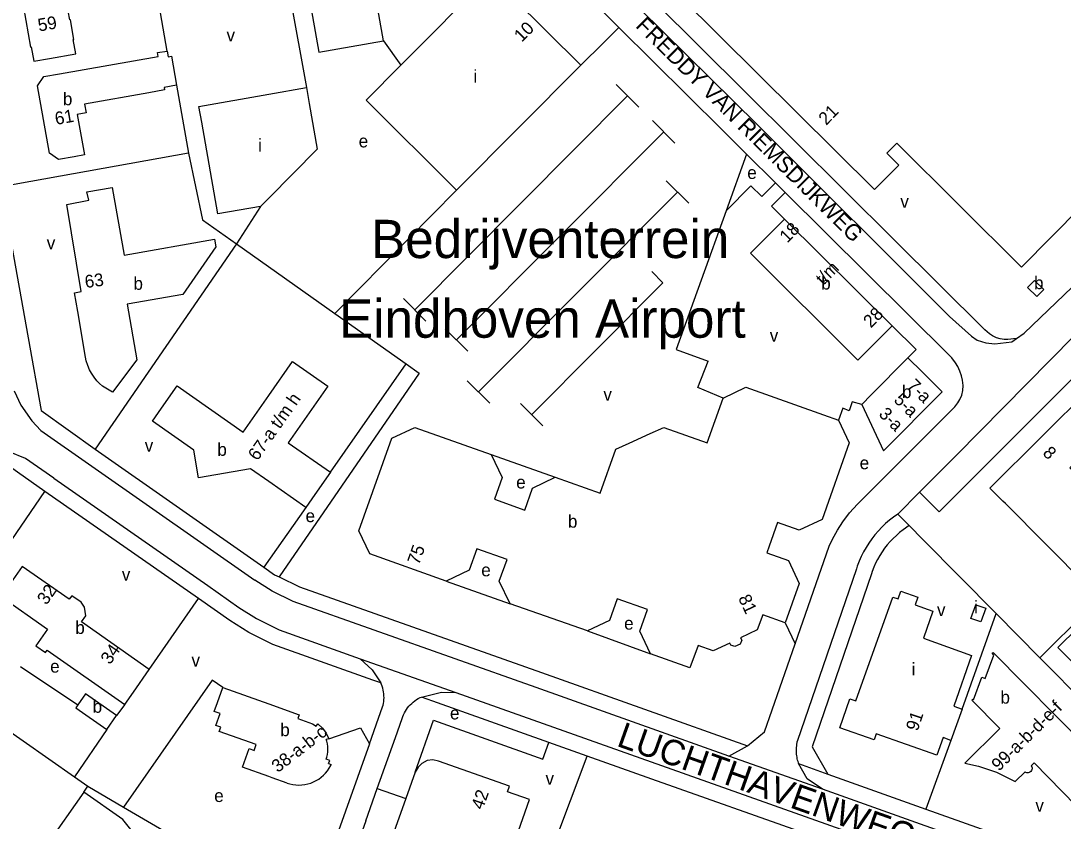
# Model space of a CAD drawing. Extents: x 154765 to 156627, y 383996 to 386132.
# Drawn here: x 155422.2 to 155749.2, y 385163.7 to 385414.8 of the extents above; entities that cross this region are included whole.
import ezdxf

# ---------------------------------------------------------------- set-up
doc = ezdxf.new("R2010")
doc.units = 0
for name, color, linetype in [('BLT_Basislijn', 7, 'Continuous'), ('BLT_Bebouwing', 7, 'Continuous'), ('BLT_Centroide', 7, 'Continuous'), ('BLT_Huisnummer', 7, 'Continuous'), ('BLT_Huisnummer_reeks', 7, 'Continuous'), ('BLT_Onderverdeling_panden', 7, 'Continuous'), ('BLT_Sport_parknaam', 7, 'Continuous'), ('BLT_Straatnaam', 7, 'Continuous'), ('BLT_Straatnaam_hoofdweg', 7, 'Continuous'), ('BLT_Vlakafsluiter', 7, 'Continuous')]:
    doc.layers.add(name, color=color, linetype=linetype)

msp = doc.modelspace()

# ---------------------------------------------------------------- linework, layer by layer
at = {"layer": 'BLT_Basislijn'}
for p, q in [((155468.15, 385405.36), (155460.46, 385448.85)), ((155506.52, 385423.64), (155511.8, 385393.87)), ((155604.99, 385407.95), (155609.89, 385412.76)), ((155536.01, 385408.59), (155541.46, 385400.93)), ((155597.88, 385400.95), (155604.99, 385407.95)), ((155471.08, 385394.64), (155474.85, 385373.32)), ((155616.13, 385387.76), (155609.04, 385394.81)), ((155612.59, 385391.29), (155545.79, 385324.15)), ((155627.46, 385376.49), (155620.37, 385383.54)), ((155623.92, 385380.01), (155558.92, 385314.7)), ((155474.85, 385373.32), (155416.02, 385362.7)), ((155474.85, 385373.32), (155479.23, 385352.38)), ((155631.76, 385357.59), (155624.67, 385364.65)), ((155658.98, 385363.96), (155654.71, 385359.68)), ((155658.98, 385363.96), (155662.03, 385360.93)), ((155558.94, 385361.75), (155520.71, 385323.05)), ((155628.22, 385361.12), (155565.8, 385298.39)), ((155662.03, 385360.93), (155657.76, 385356.65)), ((155497.37, 385356.59), (155489.85, 385344.87)), ((155479.23, 385352.38), (155489.85, 385344.87)), ((155489.85, 385344.87), (155445.57, 385280.43)), ((155489.85, 385344.87), (155520.71, 385323.05)), ((155796.43, 385347.07), (155710.35, 385260.77)), ((155623.7, 385332.67), (155620.15, 385336.2)), ((155623.7, 385332.67), (155582.48, 385291.25)), ((155549.33, 385320.63), (155542.24, 385327.68)), ((155520.71, 385323.05), (155543.12, 385307.2)), ((155562.47, 385311.17), (155555.38, 385318.22)), ((155519.35, 385273.19), (155543.12, 385307.2)), ((155543.12, 385307.2), (155547.18, 385304.33)), ((155547.18, 385304.33), (155503.24, 385240.36)), ((155569.35, 385294.87), (155562.26, 385301.92)), ((155428.63, 385292.55), (155445.57, 385280.43)), ((155586.03, 385287.73), (155578.94, 385294.78)), ((155445.57, 385280.43), (155498.47, 385243.39)), ((155569.84, 385278.73), (155589.92, 385271.61)), ((155429.71, 385267.2), (155416.84, 385276.27)), ((155478, 385233.54), (155429.71, 385267.2)), ((155704.17, 385266.91), (155710.35, 385260.77)), ((155511.6, 385262.11), (155498.47, 385243.39)), ((155697.37, 385260.09), (155700.94, 385256.48)), ((155788.81, 385261.42), (155741.91, 385215.01)), ((155700.94, 385256.48), (155705.32, 385252.04)), ((155705.32, 385252.04), (155728.26, 385228.83)), ((155684.38, 385242.92), (155665.8, 385188.7)), ((155689.12, 385241.32), (155670.54, 385187.08)), ((155555.64, 385239.03), (155575.74, 385231.87)), ((155462.53, 385211.34), (155478, 385233.54)), ((155717.53, 385198.87), (155728.26, 385228.83)), ((155728.26, 385228.83), (155741.91, 385215.01)), ((155600, 385223.45), (155619.79, 385216.19)), ((155662.04, 385225.98), (155665.17, 385219.37)), ((155741.91, 385215.01), (155777.19, 385179.31)), ((155422.14, 385212.21), (155440.1, 385200.18)), ((155454.87, 385200.35), (155452.2, 385196.86)), ((155449.16, 385192.52), (155439.03, 385177.62)), ((155650.23, 385187.38), (155655.53, 385191.72)), ((155531.64, 385187.95), (155515.19, 385141.8)), ((155534.05, 385173.99), (155539.73, 385189.98)), ((155599.94, 385184.14), (155587.92, 385188.42)), ((155644.39, 385184.15), (155650.23, 385187.38)), ((155650.23, 385187.38), (155650.28, 385187.42)), ((155670.54, 385187.08), (155675.4, 385178.45)), ((155714.02, 385189.06), (155706.21, 385167.51)), ((155588.82, 385154.61), (155599.94, 385184.14)), ((155666.26, 385181.84), (155675.4, 385178.45)), ((155675.4, 385178.45), (155706.21, 385167.51)), ((155530.45, 385163.87), (155534.05, 385173.99))]:
    msp.add_line(p, q, dxfattribs=at)
for points in [[(155609.89, 385412.76), (155575.43, 385447), (155566.59, 385455.92), (155565.51, 385457), (155564.19, 385458.03), (155562.99, 385458.85), (155561.59, 385459.71), (155560.11, 385460.47), (155558.02, 385461.34), (155555.91, 385462.06), (155552.98, 385462.73), (155550.98, 385462.93), (155548.56, 385463.03), (155547.68, 385462.98)], [(155734.6, 385315.13), (155731.84, 385314.84), (155730.71, 385314.86), (155729.51, 385315.05), (155728.37, 385315.4), (155727.12, 385315.99), (155726.14, 385316.67), (155724.68, 385317.83), (155696.18, 385346.15), (155649.48, 385392.56), (155621.13, 385420.73), (155611.87, 385429.93)], [(155608.96, 385426.03), (155653.28, 385382.33), (155713.58, 385322.08), (155720.5, 385315.89), (155722.31, 385314.59), (155724.99, 385313.76), (155727.79, 385313.46), (155733.17, 385314.1), (155734.6, 385315.13)], [(155649.88, 385372.98), (155642.14, 385380.78), (155609.89, 385412.76)], [(155734.6, 385315.13), (155737.02, 385316.87), (155752.07, 385331.32), (155809.42, 385389.71), (155810.63, 385390.94)], [(155649.88, 385372.98), (155643.48, 385355.22)], [(155658.98, 385363.96), (155649.88, 385372.98)], [(155416.02, 385362.7), (155424.54, 385315.33), (155428.63, 385292.55)], [(155654.71, 385359.68), (155651.28, 385363.08), (155643.48, 385355.22)], [(155665.17, 385219.37), (155675.84, 385250), (155676.37, 385251.16), (155677.39, 385253.13), (155678.43, 385255.01), (155680.11, 385257.59), (155682.25, 385260.45), (155684.71, 385263.14), (155715.22, 385293.74), (155716.19, 385295), (155716.84, 385296.06), (155717.42, 385297.43), (155717.73, 385298.8), (155717.86, 385300.44), (155717.7, 385302.04), (155717.39, 385303.43), (155716.86, 385304.96), (155716.2, 385306.38), (155715.48, 385307.56), (155714.3, 385309.05), (155713.35, 385310.04), (155662.03, 385360.93)], [(155643.48, 385355.22), (155627.79, 385311.76), (155637.82, 385308)], [(155661.8, 385352.64), (155657.76, 385356.65)], [(155715.76, 385278.56), (155752.64, 385315.9), (155766.75, 385330.32)], [(155695.55, 385319.16), (155703.11, 385311.66), (155700.55, 385309.08)], [(155642.56, 385296.45), (155634.6, 385299.76), (155637.82, 385308)], [(155420.11, 385298.76), (155422.23, 385294.2), (155425.65, 385289.38), (155428.46, 385286.31), (155495.6, 385239.29)], [(155686.07, 385294.48), (155683.09, 385295.32), (155682.12, 385292.5), (155680.12, 385293.28), (155678.73, 385289.55)], [(155432.59, 385271.29), (155423.74, 385277.53), (155418.53, 385279.58), (155413.38, 385280.64), (155408.56, 385281.41)], [(155715.76, 385278.56), (155713.88, 385276.66), (155704.17, 385266.91)], [(155432.59, 385271.29), (155480.88, 385237.63), (155490.58, 385230.81), (155496.21, 385227.28), (155503.26, 385223.74), (155528.74, 385214.67)], [(155393.24, 385209.32), (155391.13, 385210.77), (155429.71, 385267.2)], [(155704.17, 385266.91), (155697.37, 385260.09)], [(155697.37, 385260.09), (155696.05, 385259.15), (155694.77, 385258.16), (155693.55, 385257.1), (155692.37, 385255.98), (155691.26, 385254.81), (155690.2, 385253.58), (155689.21, 385252.31), (155688.28, 385250.98), (155687.41, 385249.61), (155686.62, 385248.2), (155685.89, 385246.75), (155685.24, 385245.27), (155684.66, 385243.76), (155684.38, 385242.92)], [(155700.94, 385256.48), (155699.03, 385255.14), (155697.94, 385254.29), (155696.91, 385253.4), (155695.91, 385252.45), (155694.97, 385251.46), (155694.07, 385250.41), (155693.23, 385249.33), (155692.44, 385248.21), (155691.71, 385247.05), (155691.03, 385245.85), (155690.42, 385244.63), (155689.87, 385243.37), (155689.37, 385242.06), (155689.12, 385241.32)], [(155498.47, 385243.39), (155501.83, 385241.05), (155503.24, 385240.36)], [(155644.39, 385184.15), (155583.93, 385205.62), (155507.68, 385232.64), (155501.05, 385235.87), (155495.6, 385239.29)], [(155503.24, 385240.36), (155509.62, 385237.26), (155585.6, 385210.34), (155650.23, 385187.38)], [(155535.16, 385207.08), (155532.69, 385207.96), (155501.29, 385219.14), (155493.75, 385222.91), (155487.81, 385226.65), (155478, 385233.54)], [(155655.53, 385191.72), (155665.17, 385219.37)], [(155528.74, 385214.67), (155532.49, 385211.22), (155535.16, 385207.08)], [(155485.56, 385205.68), (155482.23, 385208.01), (155454.45, 385168.14)], [(155535.74, 385199.54), (155535.89, 385200.1), (155536.01, 385200.67), (155536.09, 385201.25), (155536.15, 385201.84), (155536.17, 385202.44), (155536.16, 385203.05), (155536.12, 385203.65), (155536.04, 385204.26), (155535.92, 385204.86), (155535.77, 385205.45), (155535.58, 385206.04), (155535.37, 385206.61), (155535.16, 385207.08)], [(155547.94, 385202.67), (155554.23, 385204.19), (155558.69, 385204.04)], [(155558.69, 385204.04), (155671.59, 385164), (155719.27, 385147.11), (155745.95, 385136.27), (155751.44, 385134.14)], [(155541.87, 385195.98), (155542.07, 385196.55), (155542.3, 385197.11), (155542.56, 385197.67), (155542.86, 385198.21), (155543.2, 385198.75), (155543.57, 385199.26), (155543.97, 385199.76), (155544.4, 385200.23), (155544.86, 385200.68), (155545.34, 385201.1), (155545.85, 385201.49), (155546.38, 385201.85), (155546.93, 385202.18), (155547.49, 385202.47), (155547.94, 385202.67)], [(155587.92, 385188.42), (155551.45, 385201.4), (155547.94, 385202.67)], [(155531.64, 385187.95), (155534.49, 385196.06), (155535.74, 385199.54)], [(155539.73, 385189.98), (155541.87, 385195.98)], [(155545.92, 385179.11), (155551.69, 385195.36), (155586.05, 385183.15), (155587.92, 385188.42)], [(155518.87, 385189.59), (155528.78, 385192.95), (155531.64, 385187.95)], [(155666.26, 385181.84), (155666.21, 385181.98), (155666.07, 385182.42), (155665.95, 385182.86), (155665.84, 385183.31), (155665.75, 385183.77), (155665.68, 385184.23), (155665.63, 385184.69), (155665.6, 385185.14), (155665.59, 385185.6), (155665.59, 385186.06), (155665.61, 385186.51), (155665.8, 385188.7)], [(155669.92, 385159.28), (155620.24, 385176.93), (155599.94, 385184.14)], [(155673.76, 385173.72), (155668.95, 385177.02), (155666.26, 385181.84)], [(155443.27, 385174.66), (155454.45, 385168.14)], [(155534.05, 385173.99), (155542.97, 385170.82)], [(155755.57, 385147.79), (155746.1, 385149.29), (155734.81, 385152.01), (155728.35, 385154.34), (155704.53, 385162.79), (155673.76, 385173.72)], [(155454.45, 385168.14), (155481.31, 385152.46), (155515.19, 385141.8)], [(155706.21, 385167.51), (155730.03, 385159.05), (155748.54, 385152.39), (155749.64, 385152.13)], [(155530.45, 385163.87), (155526.46, 385152.67), (155523.46, 385144.21), (155522.69, 385142.05)]]:
    msp.add_lwpolyline(points, dxfattribs=at)
at = {"layer": 'BLT_Bebouwing'}
for p, q in [((155597.88, 385400.95), (155569.49, 385429.14)), ((155465.1, 385404.85), (155468.15, 385405.36)), ((155558.94, 385361.75), (155597.88, 385400.95)), ((155500, 385391.79), (155511.8, 385393.87)), ((155693.91, 385373.34), (155697.02, 385376.46)), ((155697.02, 385376.46), (155716.59, 385357.03)), ((155700.55, 385309.08), (155705.11, 385304.56)), ((155711.3, 385298.41), (155705.11, 385304.56)), ((155731.12, 385263.35), (155757.2, 385237.1)), ((155727.29, 385216.68), (155764.2, 385179.29)), ((155720.64, 385201.69), (155729.43, 385192.8)), ((155449.16, 385192.52), (155452.2, 385196.86)), ((155413.9, 385195.2), (155439.03, 385177.62)), ((155729.43, 385192.8), (155718.42, 385181.91)), ((155740.13, 385181.99), (155753.34, 385168.55)), ((155439.03, 385177.62), (155443.27, 385174.66))]:
    msp.add_line(p, q, dxfattribs=at)
for points in [[(155536.01, 385408.59), (155531.6, 385433.44), (155536.17, 385434.12), (155541.26, 385433.17), (155542.97, 385447.47), (155539.09, 385447.76), (155535.73, 385447.91), (155532.18, 385447.51), (155532.08, 385446.13), (155530.99, 385445.13), (155529.44, 385444.32), (155528.08, 385444.39), (155526.84, 385444.92), (155525.96, 385446.13), (155525.7, 385446.41), (155522.21, 385445.52), (155519.04, 385444.2), (155515.87, 385442.87), (155513, 385441.15), (155510.11, 385438.88)], [(155422.54, 385423.48), (155422.32, 385423.45), (155425.29, 385406.62), (155425.49, 385406.64), (155426.29, 385402.17), (155431.21, 385403.03), (155439.48, 385404.47), (155438.67, 385408.98), (155438.86, 385409.02), (155437.78, 385415.19), (155437.56, 385415.16), (155437.1, 385417.87), (155439.79, 385418.33), (155439.86, 385418.16), (155451.73, 385420.27), (155456.65, 385421.14), (155456.61, 385421.36), (155461.12, 385422.1), (155458.81, 385435.33), (155454.33, 385434.53), (155454.31, 385434.73), (155426.84, 385429.85), (155426.87, 385429.64)], [(155510.96, 385432.23), (155515.76, 385405.01), (155536.01, 385408.59)], [(155569.49, 385429.14), (155541.46, 385400.93)], [(155629.15, 385422.38), (155690.08, 385361.91), (155697.7, 385369.56), (155693.91, 385373.34)], [(155471.08, 385394.64), (155467.16, 385393.87), (155467.29, 385393.14), (155462.37, 385392.27), (155442.25, 385388.69), (155442.74, 385385.95), (155439.94, 385385.41), (155442.17, 385372.77), (155438.99, 385372.21), (155434.07, 385371.34), (155431.19, 385373.35), (155427.44, 385394.45), (155429.45, 385397.35), (155434.38, 385398.22), (155465.33, 385403.66), (155465.1, 385404.85)], [(155468.15, 385405.36), (155468.46, 385403.55), (155469.48, 385403.7), (155471.08, 385394.64)], [(155541.46, 385400.93), (155530.56, 385389.95), (155558.94, 385361.75)], [(155716.59, 385357.03), (155736.15, 385337.59), (155764.23, 385365.84), (155771.27, 385358.84), (155803.43, 385391.18), (155796.34, 385398.22), (155799.88, 385401.72)], [(155511.8, 385393.87), (155512.67, 385388.95), (155515.23, 385374.55), (155500, 385359.23), (155497.37, 385356.59)], [(155497.37, 385356.59), (155484.02, 385354.31), (155478.99, 385383), (155478.12, 385387.92), (155500, 385391.79)], [(155450.93, 385362.54), (155454.69, 385341.27), (155483.03, 385346.28), (155483.44, 385343.9), (155473.02, 385329.01), (155455.56, 385325.91), (155458.62, 385308.45), (155450.96, 385298.31), (155447.87, 385300.21), (155446.91, 385301.07), (155446.1, 385301.89), (155445.23, 385303), (155444.38, 385304.28), (155443.79, 385305.37), (155443.22, 385306.68), (155442.77, 385308.11), (155442.51, 385309.3), (155440.16, 385323.66), (155439.1, 385329.48), (155441.2, 385329.86), (155436.62, 385357.26), (155443.58, 385358.52), (155442.96, 385361.14), (155450.93, 385362.54)], [(155661.8, 385352.64), (155651.13, 385341.89), (155684.87, 385308.4), (155695.55, 385319.16)], [(155695.55, 385319.16), (155661.8, 385352.64)], [(155500, 385297.33), (155507.44, 385307.94), (155518.51, 385300.16), (155506.07, 385282.47), (155519.35, 385273.19)], [(155700.55, 385309.08), (155689.03, 385297.46)], [(155511.6, 385262.11), (155500, 385270.25), (155494.29, 385274.25), (155477.95, 385271.43), (155476.5, 385280.08), (155463.51, 385289.2), (155466.38, 385293.3), (155471.31, 385300.33), (155491.93, 385285.82), (155500, 385297.33)], [(155642.56, 385296.45), (155649.68, 385299.87), (155674.02, 385291.22), (155678.73, 385289.55)], [(155686.07, 385294.48), (155692.92, 385279.91), (155711.3, 385298.41)], [(155726.28, 385268.19), (155742.47, 385284.29), (155757.61, 385299.32), (155761.13, 385295.77), (155766.88, 385289.95), (155751.34, 385274.61), (155757.26, 385268.66), (155772.77, 385283.98), (155788.35, 385268.01)], [(155589.92, 385271.61), (155603.99, 385266.63), (155608.87, 385280.41), (155613.13, 385282.35), (155619.67, 385285.33), (155623.92, 385287.26), (155637.58, 385282.42), (155642.56, 385296.45)], [(155689.03, 385297.46), (155686.07, 385294.48)], [(155678.73, 385289.55), (155682.14, 385282.38), (155673.6, 385258.37), (155666.44, 385254.98), (155659.65, 385257.4), (155657.02, 385250), (155656.27, 385247.87), (155663.04, 385245.47), (155666.45, 385238.31), (155662.04, 385225.98)], [(155555.64, 385239.03), (155531.67, 385247.59), (155530.52, 385250), (155528.26, 385254.77), (155529.94, 385259.48), (155538.64, 385283.84), (155545.79, 385287.23), (155569.84, 385278.73)], [(155569.84, 385278.73), (155573.24, 385271.59), (155570.8, 385264.72), (155580.31, 385261.35), (155582.75, 385268.22), (155589.92, 385271.61)], [(155519.35, 385273.19), (155514.47, 385266.21), (155511.6, 385262.11)], [(155731.12, 385263.35), (155730.33, 385264.14), (155726.28, 385268.19)], [(155575.74, 385231.87), (155572.34, 385239.05), (155574.76, 385245.82), (155565.24, 385249.21), (155562.85, 385242.43), (155555.64, 385239.03)], [(155438.2, 385234.47), (155437.39, 385233.36), (155422.68, 385243.67), (155416.09, 385234.25)], [(155416.09, 385234.25), (155430.62, 385223.94), (155426.97, 385218.73), (155429.98, 385216.62), (155430.52, 385217.4), (155454.87, 385200.35)], [(155462.53, 385211.34), (155441.26, 385226.23), (155442.59, 385228.15), (155442.15, 385230.83), (155441.11, 385232.41), (155438.2, 385234.47)], [(155619.79, 385216.19), (155616.39, 385223.35), (155618.81, 385230.08), (155609.31, 385233.48), (155606.87, 385226.71), (155600, 385223.45)], [(155714.02, 385189.06), (155711.57, 385189.95), (155709.58, 385184.41), (155690.62, 385191.1), (155689.96, 385189.2), (155679.15, 385193.05), (155682.37, 385202.1), (155684.21, 385201.44), (155695.76, 385234.05), (155697.44, 385233.46), (155698.32, 385235.93), (155703.69, 385234.04), (155702.81, 385231.55), (155708.37, 385229.58), (155705.39, 385221.12), (155720.5, 385215.65), (155714.91, 385199.8), (155717.53, 385198.87)], [(155600, 385223.45), (155575.74, 385231.87)], [(155662.04, 385225.98), (155654.98, 385228.47), (155653.26, 385223.7), (155648.05, 385221.21), (155648.39, 385220.5), (155647.94, 385219.25), (155646.27, 385218.48), (155645.01, 385218.9), (155644.69, 385219.61), (155639.45, 385217.14), (155634.69, 385218.86), (155632.14, 385211.78), (155619.79, 385216.19)], [(155720.64, 385201.69), (155720.95, 385202.03), (155721.15, 385201.82), (155723.76, 385208.9), (155724.83, 385208.49), (155727.54, 385215.82), (155726.98, 385216.38), (155727.29, 385216.68)], [(155454.87, 385200.35), (155457.53, 385204.15), (155462.53, 385211.34)], [(155452.2, 385196.86), (155442.52, 385203.63), (155440.1, 385200.18)], [(155505.76, 385175.69), (155501.05, 385177.36), (155500, 385177.74), (155491.82, 385180.64), (155493.91, 385186.48), (155495.43, 385185.94), (155496.08, 385187.76), (155484.45, 385191.89), (155484.93, 385193.24), (155483.39, 385193.78), (155484.73, 385197.51), (155482.89, 385198.16), (155483.89, 385200.97), (155485.56, 385205.68)], [(155485.56, 385205.68), (155500, 385200.53), (155509.52, 385197.13)], [(155440.1, 385200.18), (155439.48, 385199.3), (155449.16, 385192.52)], [(155509.52, 385197.13), (155509.11, 385195.98), (155513.76, 385194.24), (155514.88, 385193.53), (155515.41, 385194.25), (155516.87, 385192.94), (155518.02, 385191.37), (155518.87, 385189.59)], [(155717.53, 385198.87), (155714.02, 385189.06)], [(155519.12, 385182.8), (155518.03, 385183.17), (155518.23, 385183.78), (155518.42, 385184.62), (155518.53, 385185.47), (155518.56, 385186.33), (155518.52, 385187.18), (155518.39, 385188.03), (155518.18, 385188.87), (155518.04, 385189.31)], [(155518.87, 385189.59), (155518.04, 385189.31)], [(155505.76, 385175.69), (155506.67, 385175.41), (155507.59, 385175.21), (155508.53, 385175.09), (155509.47, 385175.05), (155510.42, 385175.09), (155511.36, 385175.21), (155512.28, 385175.4), (155513.19, 385175.68), (155514.07, 385176.03), (155514.91, 385176.45), (155515.72, 385176.94), (155516.48, 385177.5), (155517.2, 385178.12), (155517.85, 385178.8), (155518.45, 385179.54), (155518.98, 385180.32), (155519.45, 385181.14), (155519.63, 385181.5)], [(155518.78, 385181.79), (155519.12, 385182.8)], [(155518.78, 385181.79), (155519.63, 385181.5)], [(155551.44, 385182.95), (155549.7, 385182.71), (155548.02, 385181.86), (155546.85, 385180.69), (155545.92, 385179.11)], [(155577.59, 385158.61), (155581.82, 385170.48), (155574.93, 385172.93), (155575.55, 385174.67), (155553.22, 385182.59), (155551.44, 385182.95)], [(155718.42, 385181.91), (155722.65, 385181), (155728.32, 385179.08), (155734.2, 385176.12)], [(155740.13, 385181.99), (155739.24, 385181.09), (155739.42, 385180.78), (155739.5, 385180.48), (155739.5, 385180.17), (155739.45, 385179.89), (155739.35, 385179.62), (155739.1, 385179.31), (155738.84, 385179.1), (155738.54, 385178.96), (155738.23, 385178.92), (155737.89, 385178.93), (155737.58, 385179.03), (155737.32, 385179.19), (155734.2, 385176.12)], [(155545.92, 385179.11), (155542.97, 385170.82)], [(155442.01, 385172.85), (155443.27, 385174.66)], [(155428.3, 385153.34), (155446.72, 385140.34), (155459.18, 385158.04), (155454.27, 385164.27), (155442.01, 385172.85)], [(155542.97, 385170.82), (155534.94, 385148.2)]]:
    msp.add_lwpolyline(points, dxfattribs=at)
for points in [[(155738.1, 385331.21), (155740.29, 385333.4), (155743.19, 385330.51), (155741.02, 385328.33)], [(155721.84, 385231.59), (155724.96, 385230.54), (155723.42, 385226.24), (155720.3, 385227.32)], [(155753.85, 385224.43), (155747.62, 385218.24), (155751.76, 385214.07), (155753.9, 385216.2), (155756.03, 385214.06), (155760.12, 385218.12)]]:
    msp.add_lwpolyline(points, close=True, dxfattribs=at)
at = {"layer": 'BLT_Onderverdeling_panden'}
msp.add_line((155442.01, 385172.85), (155428.3, 385153.34), dxfattribs=at)
at = {"layer": 'BLT_Vlakafsluiter'}
for p, q in [((155528.74, 385214.67), (155558.69, 385204.04)), ((155673.76, 385173.72), (155644.39, 385184.15))]:
    msp.add_line(p, q, dxfattribs=at)

# ---------------------------------------------------------------- texts
at = {"layer": 'BLT_Centroide'}
for s, p in [('v', (155486.76, 385408.41)), ('i', (155564.22, 385395.45)), ('b', (155435.42, 385388.34)), ('i', (155496.67, 385373.83)), ('e', (155528.23, 385375.12)), ('e', (155650.14, 385365.23)), ('v', (155698.16, 385356.17)), ('v', (155430.36, 385343.16)), ('b', (155457.56, 385330.44)), ('b', (155673.34, 385330.53)), ('b', (155740.11, 385330.63)), ('v', (155657.2, 385314.16)), ('v', (155605, 385295.67)), ('b', (155698.69, 385296.45)), ('v', (155461.1, 385279.61)), ('b', (155483.88, 385278.34)), ('e', (155685.41, 385274.13)), ('e', (155577.64, 385268.09)), ('e', (155511.56, 385257.54)), ('b', (155593.87, 385255.81)), ('e', (155566.68, 385240.54)), ('v', (155453.91, 385239.19)), ('i', (155721.29, 385228.91)), ('v', (155709.66, 385228.07)), ('b', (155439.31, 385222.47)), ('e', (155611.51, 385223.81)), ('e', (155431.43, 385210.32)), ('v', (155475.77, 385212.23)), ('i', (155701.69, 385209.45)), ('b', (155729.58, 385200.6)), ('b', (155444.76, 385197.73)), ('e', (155556.87, 385195.64)), ('b', (155503.62, 385190.38)), ('v', (155586.85, 385175.17)), ('e', (155482.9, 385169.73)), ('v', (155740.53, 385166.68))]:
    msp.add_text(s, height=4, dxfattribs=at).set_placement(p)
at = {"layer": 'BLT_Huisnummer'}
for s, rotation, p in [('59', 9.917, (155427.92, 385411.46)), ('10', 45.1943, (155579.37, 385407.93)), ('61', 9.9728, (155433.26, 385382.17)), ('21', 45.4541, (155674.91, 385381.89)), ('63', 7.5117, (155442.54, 385330.98)), ('8', 315.0362, (155742.58, 385278.97)), ('91', 71.0863, (155703.55, 385191.72)), ('42', 70.3939, (155567.15, 385167.09))]:
    msp.add_text(s, height=4, rotation=rotation, dxfattribs=at).set_placement(p)
at = {"layer": 'BLT_Huisnummer_reeks'}
for s, rotation, p in [('18', 45.2086, (155662.68, 385344.96)), ('t/m', 45.2191, (155674, 385331.67)), ('28', 45.2191, (155688.93, 385318.29)), ('7-a', 315.2006, (155700.03, 385300.07)), ('5-a', 315.2006, (155695.86, 385295.62)), ('67-a t/m h', 55.0267, (155496.46, 385276.57)), ('3-a', 315.2006, (155691.15, 385291.18)), ('75', 70.5821, (155547.13, 385243.91)), ('32', 55.0161, (155430.27, 385231.32)), ('81', 295.3881, (155647.21, 385233.71)), ('34', 55.1757, (155450.21, 385212.61)), ('99-a-b-d-e-f', 44.5738, (155729.12, 385179.2)), ('38-a-b-c', 37.7037, (155502.84, 385178.78))]:
    msp.add_text(s, height=4, rotation=rotation, dxfattribs=at).set_placement(p)
at = {"layer": 'BLT_Sport_parknaam'}
for s, p in [('Bedrijventerrein', (155532.11, 385340.4)), ('Eindhoven Airport', (155522.07, 385315.4))]:
    msp.add_text(s, height=12, dxfattribs=at).set_placement(p)
at = {"layer": 'BLT_Straatnaam'}
msp.add_text('FREDDY VAN RIEMSDIJKWEG', height=5, rotation=315.2104, dxfattribs=at).set_placement((155614.87, 385413.01))
at = {"layer": 'BLT_Straatnaam_hoofdweg'}
msp.add_text('LUCHTHAVENWEG', height=8, rotation=340.4457, dxfattribs=at).set_placement((155608.83, 385187.42))

doc.saveas('drawing.dxf')
